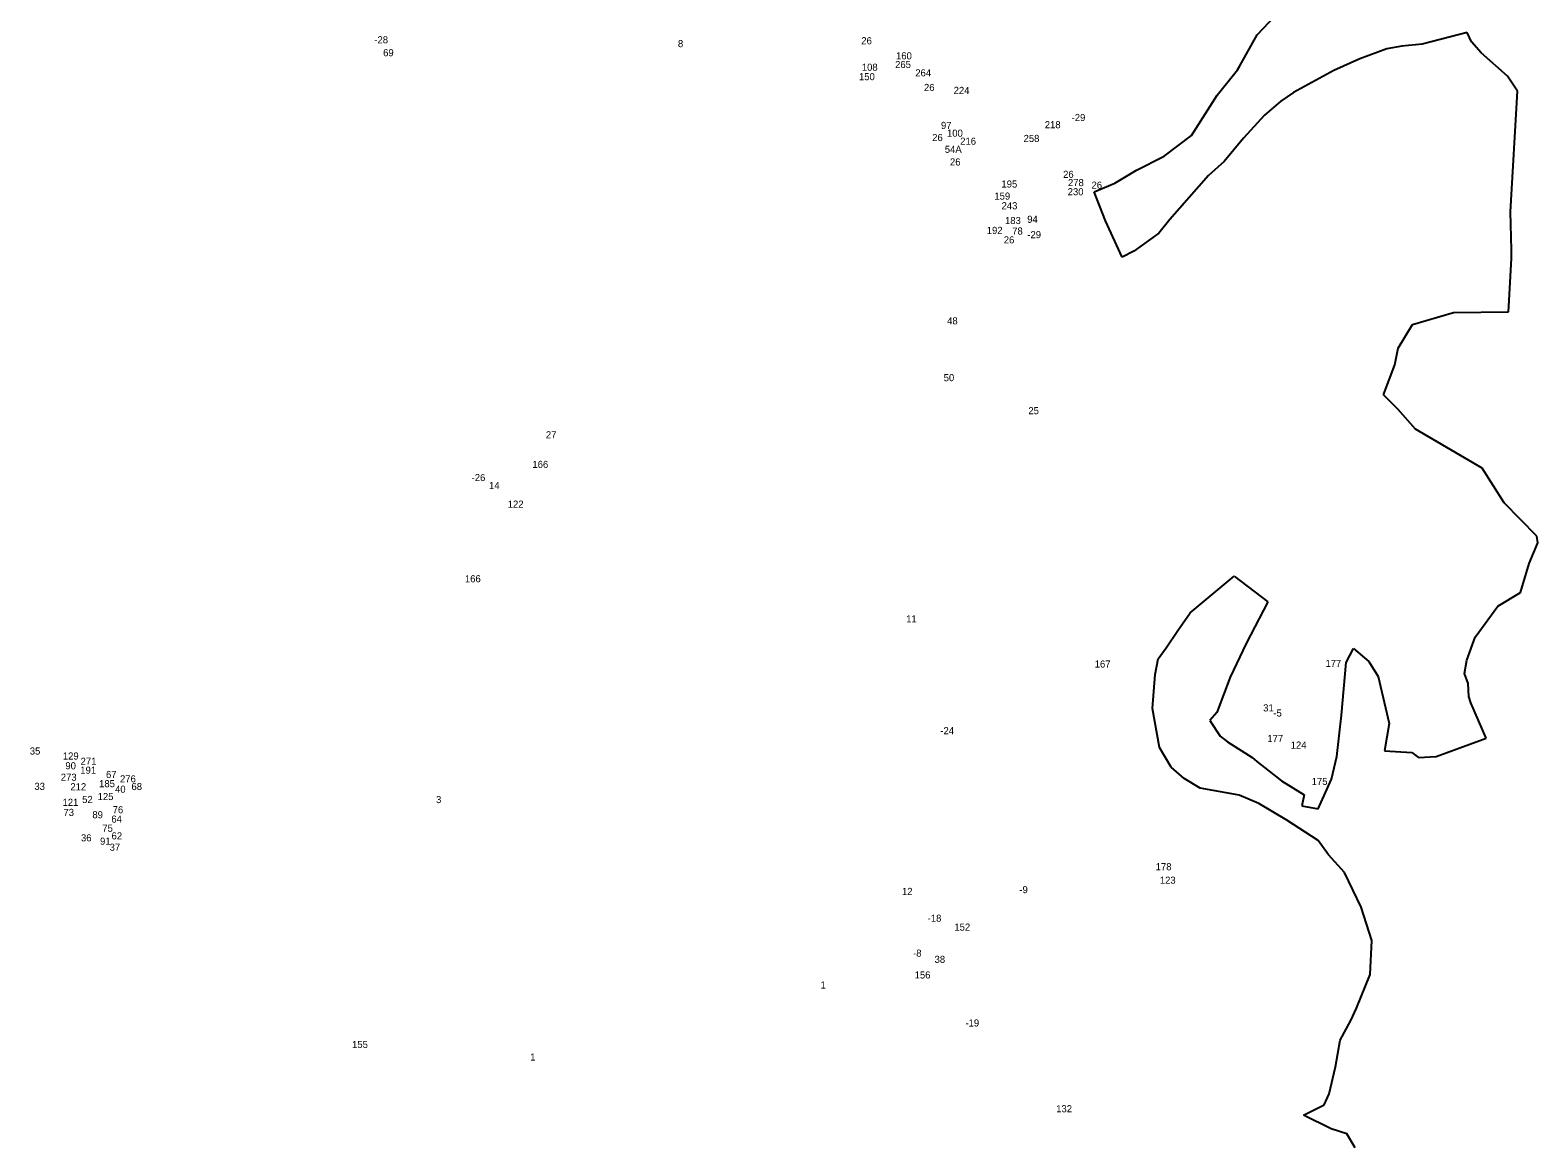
# Model space of a CAD drawing. Extents: x -787692 to -782531, y -972586 to -966265.
# Drawn here: x -785127 to -783001, y -969423 to -967858 of the extents above; entities that cross this region are included whole.
import ezdxf

# ---------------------------------------------------------------- set-up
doc = ezdxf.new("R2010")
doc.units = 0
for name, color, linetype in [('Vrstva 13', 7, 'Continuous'), ('Vrstva 15', 7, 'Continuous'), ('Vrstva 24', 7, 'Continuous')]:
    doc.layers.add(name, color=color, linetype=linetype)

msp = doc.modelspace()

# ---------------------------------------------------------------- linework, layer by layer
at = {"layer": 'Vrstva 13'}
for p, q in [((-783396.91, -967864.34), (-783363.36, -967829.15)), ((-783421.08, -967908.12), (-783396.91, -967864.34)), ((-783100.96, -967860.94), (-783164.16, -967877.51)), ((-783094.66, -967874.01), (-783100.96, -967860.94)), ((-783213.87, -967884.26), (-783252.23, -967898.01)), ((-783192.99, -967880.31), (-783213.87, -967884.26)), ((-783164.16, -967877.51), (-783192.99, -967880.31)), ((-783081.23, -967889.56), (-783094.66, -967874.01)), ((-783252.23, -967898.01), (-783288.67, -967914.8)), ((-783044, -967922.68), (-783081.23, -967889.56)), ((-783453.08, -967949.16), (-783424.8, -967913.68)), ((-783424.8, -967913.68), (-783421.08, -967908.12)), ((-783288.67, -967914.8), (-783345.57, -967945.68)), ((-783029.77, -967943.78), (-783044, -967922.68)), ((-783489.43, -968006.35), (-783453.08, -967949.16)), ((-783345.57, -967945.68), (-783363.53, -967957.6)), ((-783039.55, -968113.56), (-783029.77, -967943.78)), ((-783363.53, -967957.6), (-783386.72, -967977.36)), ((-783386.72, -967977.36), (-783416.1, -968010.17)), ((-783528.04, -968035.26), (-783489.43, -968006.35)), ((-783416.1, -968010.17), (-783443.54, -968042.96)), ((-783597.49, -968073.21), (-783567.14, -968055.18)), ((-783567.14, -968055.18), (-783528.04, -968035.26)), ((-783443.54, -968042.96), (-783465.39, -968062.7)), ((-783626.83, -968085.47), (-783597.49, -968073.21)), ((-783465.39, -968062.7), (-783520.19, -968124.59)), ((-783610.88, -968126.61), (-783626.83, -968085.47)), ((-783038.14, -968167.35), (-783039.55, -968113.56)), ((-783587.29, -968177.7), (-783610.88, -968126.61)), ((-783520.19, -968124.59), (-783535.49, -968144.02)), ((-783535.49, -968144.02), (-783570.53, -968169.12)), ((-783570.53, -968169.12), (-783587.29, -968177.7)), ((-783041.62, -968238.72), (-783038.38, -968179.29)), ((-783038.38, -968179.29), (-783038.14, -968167.35)), ((-783042.32, -968254.6), (-783041.62, -968238.72)), ((-783178.04, -968272.39), (-783120.1, -968255.41)), ((-783120.1, -968255.41), (-783042.32, -968254.6)), ((-783198.17, -968305.74), (-783178.04, -968272.39)), ((-783202.86, -968329.23), (-783198.17, -968305.74)), ((-783218.65, -968371.67), (-783202.86, -968329.23)), ((-783198.33, -968391.67), (-783218.65, -968371.67)), ((-783173.85, -968419.84), (-783198.33, -968391.67)), ((-783079.89, -968475.16), (-783173.85, -968419.84)), ((-783048.86, -968523.96), (-783079.89, -968475.16)), ((-783002.81, -968571), (-783048.86, -968523.96)), ((-783013.22, -968609.55), (-783001.16, -968580.41)), ((-783001.16, -968580.41), (-783002.81, -968571)), ((-783491.11, -968679.04), (-783429.44, -968627.1)), ((-783429.44, -968627.1), (-783381.69, -968663.25)), ((-783025.52, -968650.37), (-783013.22, -968609.55)), ((-783057.4, -968669.3), (-783025.52, -968650.37)), ((-783381.69, -968663.25), (-783412.28, -968722.15)), ((-783089.45, -968713.02), (-783057.4, -968669.3)), ((-783508.5, -968703.81), (-783491.11, -968679.04)), ((-783525.33, -968728.26), (-783508.5, -968703.81)), ((-783101.43, -968745.57), (-783089.45, -968713.02)), ((-783536.41, -968743.8), (-783525.33, -968728.26)), ((-783412.28, -968722.15), (-783434.93, -968769.71)), ((-783271.61, -968749.07), (-783261, -968729.07)), ((-783261, -968729.07), (-783239.26, -968747.45)), ((-783540.46, -968765.98), (-783536.41, -968743.8)), ((-783277.76, -968823.19), (-783271.61, -968749.07)), ((-783239.26, -968747.45), (-783226.3, -968768.75)), ((-783104.67, -968764.55), (-783101.43, -968745.57)), ((-783544.62, -968813.93), (-783540.46, -968765.98)), ((-783434.93, -968769.71), (-783453.95, -968819.26)), ((-783226.3, -968768.75), (-783210.59, -968834.9)), ((-783099.6, -968778.26), (-783104.67, -968764.55)), ((-783098.43, -968797), (-783099.6, -968778.26)), ((-783095.84, -968805.66), (-783098.43, -968797)), ((-783534.79, -968868.55), (-783544.62, -968813.93)), ((-783453.95, -968819.26), (-783463.41, -968830.51)), ((-783074.23, -968855.61), (-783095.84, -968805.66)), ((-783463.41, -968830.51), (-783449.1, -968852.95)), ((-783284.32, -968881.4), (-783277.76, -968823.19)), ((-783210.59, -968834.9), (-783217.48, -968873.35)), ((-783449.1, -968852.95), (-783438.74, -968860.64)), ((-783438.74, -968860.64), (-783403.94, -968882.58)), ((-783144.57, -968881.23), (-783082.73, -968859.01)), ((-783082.73, -968859.01), (-783074.23, -968855.61)), ((-783518.29, -968896.55), (-783534.79, -968868.55)), ((-783403.94, -968882.58), (-783397.31, -968888.48)), ((-783291.89, -968913.28), (-783284.32, -968881.4)), ((-783217.48, -968873.35), (-783178.87, -968875.62)), ((-783178.87, -968875.62), (-783169.49, -968882.97)), ((-783169.49, -968882.97), (-783144.57, -968881.23)), ((-783499.76, -968912.58), (-783518.29, -968896.55)), ((-783397.31, -968888.48), (-783362.51, -968915.76)), ((-783477.1, -968925.91), (-783499.76, -968912.58)), ((-783422.32, -968935.86), (-783477.1, -968925.91)), ((-783362.51, -968915.76), (-783330.54, -968935.35)), ((-783310.96, -968955.27), (-783291.89, -968913.28)), ((-783394.32, -968947.79), (-783422.32, -968935.86)), ((-783355.25, -968971.09), (-783394.32, -968947.79)), ((-783330.54, -968935.35), (-783334.1, -968950.97)), ((-783334.1, -968950.97), (-783310.96, -968955.27)), ((-783310.98, -968999.84), (-783355.25, -968971.09)), ((-783296.25, -969019.92), (-783310.98, -968999.84)), ((-783273.6, -969044.93), (-783296.25, -969019.92)), ((-783250.3, -969093.64), (-783273.6, -969044.93)), ((-783235.11, -969140.72), (-783250.3, -969093.64)), ((-783237.54, -969188.69), (-783235.11, -969140.72)), ((-783256.84, -969235.91), (-783237.54, -969188.69)), ((-783264.61, -969253.64), (-783256.84, -969235.91)), ((-783279.9, -969281.15), (-783264.61, -969253.64)), ((-783286.61, -969318.95), (-783279.9, -969281.15)), ((-783295.27, -969356.79), (-783286.61, -969318.95)), ((-783331.36, -969386.74), (-783302.23, -969372.49)), ((-783302.23, -969372.49), (-783295.27, -969356.79)), ((-783292.52, -969406.16), (-783331.36, -969386.74)), ((-783270.68, -969412.96), (-783292.52, -969406.16)), ((-783258.93, -969433.08), (-783270.68, -969412.96))]:
    msp.add_line(p, q, dxfattribs=at)

# ---------------------------------------------------------------- texts
at = {"layer": 'Vrstva 15'}
for s, p in [('-28', (-784641.49, -967876.27)), ('69', (-784629.104, -967894.52)), ('8', (-784213.476, -967881.7)), ('26', (-783954.99, -967877.63)), ('108', (-783954.23, -967914.95)), ('150', (-783958.261, -967928.24)), ('26', (-783866.59, -967943.46)), ('97', (-783842.638, -967996.97)), ('-29', (-783658.424, -967985.79)), ('26', (-783855.04, -968014.05)), ('100', (-783834.151, -968007.89)), ('54A', (-783837.244, -968030.62)), ('26', (-783829.93, -968048.47)), ('26', (-783670.45, -968065.93)), ('26', (-783630.39, -968081.13)), ('94', (-783721.056, -968129.25)), ('192', (-783778.114, -968144.92)), ('183', (-783752.361, -968130.98)), ('78', (-783742.205, -968145.85)), ('-29', (-783720.884, -968150.9)), ('26', (-783754.08, -968158.25)), ('48', (-783833.962, -968272.38)), ('50', (-783838.836, -968352.44)), ('25', (-783719.406, -968398.95)), ('27', (-784399.666, -968432.98)), ('-26', (-784504.344, -968493.24)), ('14', (-784479.827, -968504.52)), ('122', (-784453.451, -968530.7)), ('11', (-783891.746, -968692.38)), ('31', (-783388.381, -968817.86)), ('-5', (-783374.04, -968825.06)), ('-24', (-783843.536, -968849.97)), ('35', (-785127.256, -968878.64)), ('129', (-785080.674, -968885.7)), ('90', (-785077.09, -968899.42)), ('67', (-785019.808, -968911.71)), ('33', (-785120.766, -968928.44)), ('40', (-785007.082, -968932.46)), ('68', (-784983.89, -968928.71)), ('121', (-785081.086, -968950.96)), ('52', (-785053.446, -968946.89)), ('125', (-785031.591, -968942.81)), ('3', (-784554.526, -968947.05)), ('73', (-785079.805, -968965.13)), ('89', (-785039.03, -968968.43)), ('64', (-785012.246, -968974.54)), ('76', (-785010.378, -968961.36)), ('36', (-785055.09, -969001.02)), ('75', (-785025.045, -968987.48)), ('62', (-785011.96, -968998.25)), ('91', (-785028.214, -969005.67)), ('37', (-785014.726, -969014.21)), ('12', (-783897.671, -969076.5)), ('-9', (-783732.074, -969074.01)), ('-18', (-783861.414, -969114.2)), ('152', (-783823.771, -969126.82)), ('-8', (-783881.95, -969163.49)), ('38', (-783851.666, -969172.2)), ('1', (-784012.541, -969208.41)), ('156', (-783879.764, -969194.23)), ('-19', (-783808.158, -969261.9)), ('155', (-784672.891, -969292.27)), ('1', (-784421.711, -969309.93))]:
    msp.add_text(s, height=10, dxfattribs=at).set_placement(p)
at = {"layer": 'Vrstva 24'}
for s, p in [('265', (-783907.31, -967911.14)), ('160', (-783906.014, -967898.91)), ('264', (-783878.856, -967922.91)), ('224', (-783824.772, -967947.63)), ('218', (-783696.311, -967995.97)), ('216', (-783815.534, -968019.18)), ('258', (-783726.156, -968015.32)), ('195', (-783757.424, -968079.56)), ('278', (-783663.595, -968077.58)), ('159', (-783767.374, -968096.56)), ('230', (-783664.006, -968090.42)), ('243', (-783757.232, -968110.19)), ('166', (-784418.658, -968474.69)), ('166', (-784513.798, -968635.83)), ('167', (-783625.913, -968756.04)), ('177', (-783300.598, -968755.15)), ('177', (-783382.518, -968860.97)), ('124', (-783349.587, -968870.27)), ('271', (-785055.66, -968893.09)), ('273', (-785083.575, -968915.6)), ('191', (-785056.088, -968905.66)), ('212', (-785070.021, -968928.99)), ('185', (-785029.541, -968924.66)), ('276', (-785000.048, -968917.83)), ('175', (-783320.04, -968921.51)), ('178', (-783539.95, -969041.66)), ('123', (-783534.121, -969060.68)), ('132', (-783680.171, -969382.76))]:
    msp.add_text(s, height=10, dxfattribs=at).set_placement(p)

doc.saveas('drawing.dxf')
